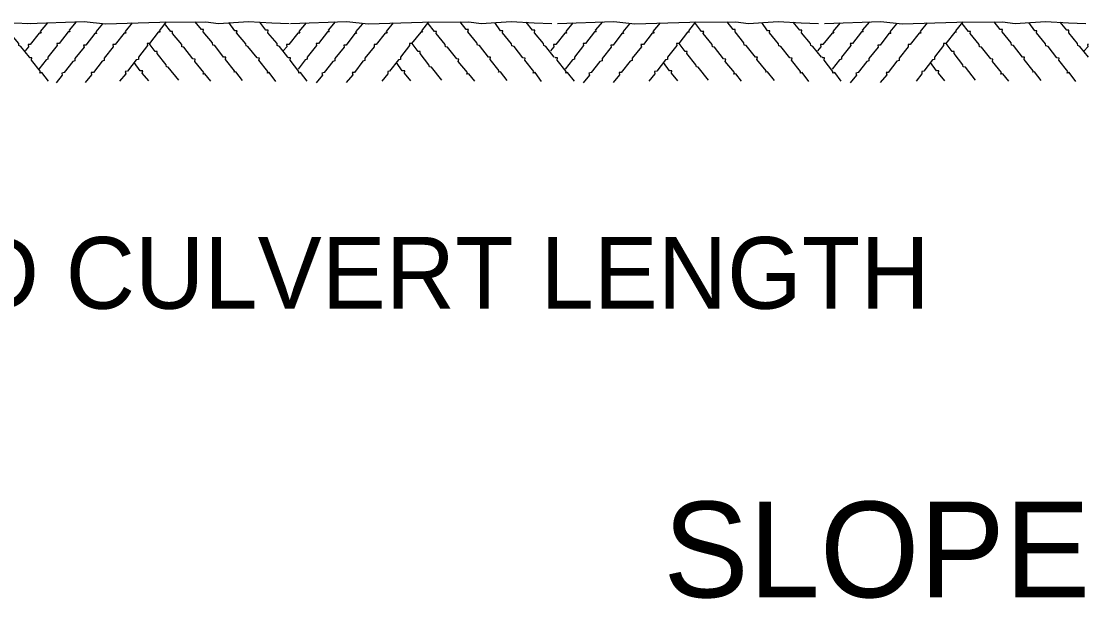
# Model space of a CAD drawing. Extents: x 49991.4 to 50021, y 49987.6 to 50011.4.
# Drawn here: x 50004.56 to 50005.452, y 49996.72 to 49997.202 of the extents above; entities that cross this region are included whole.
import ezdxf

# ---------------------------------------------------------------- set-up
doc = ezdxf.new("R2010")
doc.units = 0
doc.layers.add('Level 1', color=7, linetype='Continuous')
doc.layers.add('Level 2', color=7, linetype='Continuous')

msp = doc.modelspace()

# ---------------------------------------------------------------- linework, layer by layer
at = {"layer": 'Level 1'}
for points in [[(50004.3495, 49997.2006), (50004.3965, 49997.2025), (50004.4143, 49997.2004), (50004.4599, 49997.2019), (50004.4983, 49997.2022), (50004.5089, 49997.2007), (50004.534, 49997.2025), (50004.5533, 49997.2013), (50004.5679, 49997.2006)], [(50004.5669, 49997.1726), (50004.5597, 49997.1816), (50004.558, 49997.1822), (50004.5579, 49997.1839), (50004.5503, 49997.193), (50004.5505, 49997.195), (50004.5485, 49997.195), (50004.5433, 49997.2019)], [(50004.5655, 49997.2006), (50004.6125, 49997.2025), (50004.6303, 49997.2004), (50004.6759, 49997.2019), (50004.7143, 49997.2022), (50004.7249, 49997.2007), (50004.75, 49997.2025), (50004.7693, 49997.2013), (50004.7839, 49997.2006)], [(50004.5819, 49997.2012), (50004.5759, 49997.1941), (50004.5765, 49997.1926), (50004.5749, 49997.1926), (50004.5675, 49997.183), (50004.5665, 49997.183)], [(50004.6059, 49997.202), (50004.6, 49997.195), (50004.6005, 49997.1936), (50004.5993, 49997.1936), (50004.5917, 49997.184), (50004.5898, 49997.184), (50004.5899, 49997.1824), (50004.5823, 49997.1726), (50004.5823, 49997.171), (50004.5807, 49997.1704), (50004.5747, 49997.1626)], [(50004.6527, 49997.2012), (50004.6467, 49997.1941), (50004.6474, 49997.1926), (50004.6459, 49997.1926), (50004.6385, 49997.183), (50004.6365, 49997.183), (50004.6369, 49997.1812), (50004.6293, 49997.1718), (50004.6293, 49997.1698), (50004.6275, 49997.1692), (50004.6203, 49997.1598), (50004.6183, 49997.1598), (50004.6187, 49997.1578), (50004.6135, 49997.1515)], [(50004.6811, 49997.202), (50004.6753, 49997.1947), (50004.6761, 49997.1935), (50004.6745, 49997.1935), (50004.6671, 49997.1839), (50004.6653, 49997.1839), (50004.6654, 49997.1822), (50004.6579, 49997.1726), (50004.6579, 49997.1707), (50004.6559, 49997.1702), (50004.6489, 49997.1608), (50004.6469, 49997.1606), (50004.6474, 49997.1587), (50004.6421, 49997.1524)], [(50004.7449, 49997.153), (50004.7393, 49997.1602), (50004.7379, 49997.1599), (50004.7381, 49997.1612), (50004.7307, 49997.1706), (50004.7309, 49997.1725), (50004.7291, 49997.1726), (50004.7217, 49997.1824), (50004.72, 49997.1827), (50004.7199, 49997.1845), (50004.7121, 49997.1936), (50004.7123, 49997.1956), (50004.7105, 49997.1956), (50004.7053, 49997.202)], [(50004.7728, 49997.1522), (50004.7673, 49997.1596), (50004.7657, 49997.1592), (50004.7661, 49997.1605), (50004.7585, 49997.1701), (50004.759, 49997.1718), (50004.7571, 49997.172), (50004.7495, 49997.1816), (50004.7479, 49997.1821), (50004.7477, 49997.1838), (50004.7399, 49997.193), (50004.7404, 49997.1947), (50004.7385, 49997.1947), (50004.7335, 49997.2016)], [(50004.7829, 49997.1726), (50004.7757, 49997.1816), (50004.774, 49997.1822), (50004.7739, 49997.1839), (50004.7661, 49997.193), (50004.7665, 49997.195), (50004.7645, 49997.195), (50004.7593, 49997.2019)], [(50004.798, 49997.2012), (50004.792, 49997.1941), (50004.7927, 49997.1926), (50004.7913, 49997.1926), (50004.7837, 49997.183), (50004.7829, 49997.183)], [(50004.7849, 49997.2006), (50004.8321, 49997.2025), (50004.8499, 49997.2004), (50004.8955, 49997.2019), (50004.9341, 49997.2022), (50004.9445, 49997.2007), (50004.9695, 49997.2025), (50004.9888, 49997.2013), (50005.0035, 49997.2006)], [(50004.8225, 49997.202), (50004.8165, 49997.195), (50004.8173, 49997.1936), (50004.816, 49997.1936), (50004.8085, 49997.184), (50004.8065, 49997.184), (50004.8069, 49997.1824), (50004.7991, 49997.1726), (50004.7991, 49997.171), (50004.7974, 49997.1704), (50004.7914, 49997.1626)], [(50004.8709, 49997.2012), (50004.8649, 49997.1941), (50004.8657, 49997.1926), (50004.8641, 49997.1926), (50004.8567, 49997.183), (50004.8549, 49997.183), (50004.855, 49997.1812), (50004.8473, 49997.1718), (50004.8473, 49997.1698), (50004.8455, 49997.1692), (50004.8385, 49997.1598), (50004.8365, 49997.1598), (50004.837, 49997.1578), (50004.8317, 49997.1515)], [(50004.9003, 49997.202), (50004.8945, 49997.1947), (50004.8953, 49997.1935), (50004.8939, 49997.1935), (50004.8863, 49997.1839), (50004.8844, 49997.1839), (50004.8845, 49997.1822), (50004.8769, 49997.1726), (50004.8769, 49997.1707), (50004.8754, 49997.1702), (50004.8679, 49997.1608), (50004.8663, 49997.1606), (50004.8665, 49997.1587), (50004.8613, 49997.1524)], [(50004.9661, 49997.153), (50004.9607, 49997.1602), (50004.9589, 49997.1599), (50004.9594, 49997.1612), (50004.9519, 49997.1706), (50004.9523, 49997.1725), (50004.9504, 49997.1726), (50004.9429, 49997.1824), (50004.9413, 49997.1827), (50004.9408, 49997.1845), (50004.9333, 49997.1936), (50004.9337, 49997.1956), (50004.9318, 49997.1956), (50004.9269, 49997.202)], [(50004.9949, 49997.1522), (50004.9895, 49997.1596), (50004.9879, 49997.1592), (50004.9883, 49997.1605), (50004.9809, 49997.1701), (50004.9811, 49997.1718), (50004.9793, 49997.172), (50004.9719, 49997.1816), (50004.9701, 49997.1821), (50004.9697, 49997.1838), (50004.9623, 49997.193), (50004.9625, 49997.1947), (50004.9607, 49997.1947), (50004.9557, 49997.2016)], [(50005.0055, 49997.1726), (50004.9985, 49997.1816), (50004.9967, 49997.1822), (50004.9965, 49997.1839), (50004.9889, 49997.193), (50004.9893, 49997.195), (50004.9873, 49997.195), (50004.9821, 49997.2019)], [(50005.0211, 49997.2012), (50005.0151, 49997.1941), (50005.0158, 49997.1926), (50005.0143, 49997.1926), (50005.0069, 49997.183), (50005.0061, 49997.183)], [(50005.0081, 49997.2006), (50005.0554, 49997.2025), (50005.0729, 49997.2004), (50005.1189, 49997.2019), (50005.1573, 49997.2022), (50005.1679, 49997.2007), (50005.1928, 49997.2025), (50005.212, 49997.2013), (50005.2265, 49997.2006)], [(50005.0458, 49997.202), (50005.0398, 49997.195), (50005.0405, 49997.1936), (50005.0391, 49997.1936), (50005.0315, 49997.184), (50005.0297, 49997.184), (50005.0299, 49997.1824), (50005.0224, 49997.1726), (50005.0224, 49997.171), (50005.0207, 49997.1704), (50005.0145, 49997.1626)], [(50005.0939, 49997.2012), (50005.0879, 49997.1941), (50005.0889, 49997.1926), (50005.0873, 49997.1926), (50005.08, 49997.183), (50005.0779, 49997.183), (50005.0783, 49997.1812), (50005.0705, 49997.1718), (50005.0705, 49997.1698), (50005.0689, 49997.1692), (50005.0615, 49997.1598), (50005.0597, 49997.1598), (50005.0601, 49997.1578), (50005.0548, 49997.1515)], [(50005.1237, 49997.202), (50005.1177, 49997.1947), (50005.1184, 49997.1935), (50005.1169, 49997.1935), (50005.1095, 49997.1839), (50005.1077, 49997.1839), (50005.1079, 49997.1822), (50005.1003, 49997.1726), (50005.1003, 49997.1707), (50005.0985, 49997.1702), (50005.0913, 49997.1608), (50005.0893, 49997.1606), (50005.0897, 49997.1587), (50005.0845, 49997.1524)], [(50005.1895, 49997.153), (50005.1838, 49997.1602), (50005.1823, 49997.1599), (50005.1827, 49997.1612), (50005.1749, 49997.1706), (50005.1755, 49997.1725), (50005.1737, 49997.1726), (50005.1659, 49997.1824), (50005.1643, 49997.1827), (50005.1641, 49997.1845), (50005.1567, 49997.1936), (50005.1568, 49997.1956), (50005.155, 49997.1956), (50005.1499, 49997.202)], [(50005.2183, 49997.1522), (50005.2127, 49997.1596), (50005.2113, 49997.1592), (50005.2114, 49997.1605), (50005.2039, 49997.1701), (50005.2045, 49997.1718), (50005.2025, 49997.172), (50005.1949, 49997.1816), (50005.1933, 49997.1821), (50005.1929, 49997.1838), (50005.1853, 49997.193), (50005.1857, 49997.1947), (50005.1838, 49997.1947), (50005.1789, 49997.2016)], [(50005.2288, 49997.1726), (50005.2217, 49997.1816), (50005.2199, 49997.1822), (50005.2198, 49997.1839), (50005.2121, 49997.193), (50005.2125, 49997.195), (50005.2107, 49997.195), (50005.2053, 49997.2019)], [(50005.2444, 49997.2012), (50005.2384, 49997.1941), (50005.2391, 49997.1926), (50005.2377, 49997.1926), (50005.2301, 49997.183), (50005.2293, 49997.183)], [(50005.2315, 49997.2006), (50005.2785, 49997.2025), (50005.2963, 49997.2004), (50005.3419, 49997.2019), (50005.3803, 49997.2022), (50005.3909, 49997.2007), (50005.416, 49997.2025), (50005.4353, 49997.2013), (50005.4499, 49997.2006)], [(50005.269, 49997.202), (50005.263, 49997.195), (50005.2637, 49997.1936), (50005.2623, 49997.1936), (50005.2549, 49997.184), (50005.2528, 49997.184), (50005.2533, 49997.1824), (50005.2455, 49997.1726), (50005.2455, 49997.171), (50005.2438, 49997.1704), (50005.2378, 49997.1626)], [(50005.3173, 49997.2012), (50005.3113, 49997.1941), (50005.3119, 49997.1926), (50005.3105, 49997.1926), (50005.3031, 49997.183), (50005.3013, 49997.183), (50005.3014, 49997.1812), (50005.2937, 49997.1718), (50005.2937, 49997.1698), (50005.2919, 49997.1692), (50005.2847, 49997.1598), (50005.2829, 49997.1598), (50005.2834, 49997.1578), (50005.278, 49997.1515)], [(50005.3469, 49997.202), (50005.341, 49997.1947), (50005.3415, 49997.1935), (50005.3403, 49997.1935), (50005.3327, 49997.1839), (50005.3308, 49997.1839), (50005.3309, 49997.1822), (50005.3233, 49997.1726), (50005.3233, 49997.1707), (50005.3217, 49997.1702), (50005.3143, 49997.1608), (50005.3127, 49997.1606), (50005.3128, 49997.1587), (50005.3079, 49997.1524)], [(50005.4125, 49997.153), (50005.407, 49997.1602), (50005.4055, 49997.1599), (50005.4058, 49997.1612), (50005.3983, 49997.1706), (50005.3987, 49997.1725), (50005.3968, 49997.1726), (50005.3893, 49997.1824), (50005.3877, 49997.1827), (50005.3873, 49997.1845), (50005.3799, 49997.1936), (50005.3801, 49997.1956), (50005.3783, 49997.1956), (50005.3733, 49997.202)], [(50005.4415, 49997.1522), (50005.4358, 49997.1596), (50005.4343, 49997.1592), (50005.4347, 49997.1605), (50005.4273, 49997.1701), (50005.4275, 49997.1718), (50005.4257, 49997.172), (50005.4183, 49997.1816), (50005.4165, 49997.1821), (50005.4161, 49997.1838), (50005.4087, 49997.193), (50005.4089, 49997.1947), (50005.4071, 49997.1947), (50005.4021, 49997.2016)], [(50005.452, 49997.1726), (50005.4448, 49997.1816), (50005.4431, 49997.1822), (50005.443, 49997.1839), (50005.4355, 49997.193), (50005.4357, 49997.195), (50005.4339, 49997.195), (50005.4285, 49997.2019)], [(50004.6279, 49997.2004), (50004.6223, 49997.1936), (50004.6229, 49997.1923), (50004.6215, 49997.1923), (50004.6139, 49997.1827), (50004.6121, 49997.1827), (50004.6125, 49997.181), (50004.6048, 49997.1713), (50004.6048, 49997.1696), (50004.6031, 49997.1689), (50004.5958, 49997.1596), (50004.594, 49997.1593), (50004.5943, 49997.1576), (50004.5891, 49997.151)], [(50004.7185, 49997.1524), (50004.7135, 49997.1587), (50004.7121, 49997.1584), (50004.7125, 49997.1598), (50004.705, 49997.169), (50004.7053, 49997.171), (50004.7035, 49997.1712), (50004.696, 49997.1808), (50004.6943, 49997.1812), (50004.6941, 49997.183), (50004.6864, 49997.1922), (50004.6865, 49997.1941), (50004.6849, 49997.1941), (50004.6798, 49997.2006)], [(50004.8453, 49997.2004), (50004.8395, 49997.1936), (50004.8403, 49997.1923), (50004.8388, 49997.1923), (50004.8315, 49997.1827), (50004.8295, 49997.1827), (50004.8298, 49997.181), (50004.8221, 49997.1713), (50004.8221, 49997.1696), (50004.8205, 49997.1689), (50004.8131, 49997.1596), (50004.8113, 49997.1593), (50004.8117, 49997.1576), (50004.8064, 49997.151)], [(50004.939, 49997.1524), (50004.9341, 49997.1587), (50004.9325, 49997.1584), (50004.9329, 49997.1598), (50004.9253, 49997.169), (50004.9258, 49997.171), (50004.924, 49997.1712), (50004.9163, 49997.1808), (50004.9145, 49997.1812), (50004.9144, 49997.183), (50004.9067, 49997.1922), (50004.9071, 49997.1941), (50004.9053, 49997.1941), (50004.9001, 49997.2006)], [(50005.0683, 49997.2004), (50005.0629, 49997.1936), (50005.0635, 49997.1923), (50005.0621, 49997.1923), (50005.0547, 49997.1827), (50005.0529, 49997.1827), (50005.053, 49997.181), (50005.0455, 49997.1713), (50005.0455, 49997.1696), (50005.0435, 49997.1689), (50005.0363, 49997.1596), (50005.0345, 49997.1593), (50005.035, 49997.1576), (50005.0297, 49997.151)], [(50005.1621, 49997.1524), (50005.1573, 49997.1587), (50005.1557, 49997.1584), (50005.1561, 49997.1598), (50005.1485, 49997.169), (50005.149, 49997.171), (50005.1471, 49997.1712), (50005.1395, 49997.1808), (50005.1379, 49997.1812), (50005.1375, 49997.183), (50005.1299, 49997.1922), (50005.1304, 49997.1941), (50005.1285, 49997.1941), (50005.1235, 49997.2006)], [(50005.2917, 49997.2004), (50005.2859, 49997.1936), (50005.2869, 49997.1923), (50005.2853, 49997.1923), (50005.278, 49997.1827), (50005.2759, 49997.1827), (50005.2763, 49997.181), (50005.2685, 49997.1713), (50005.2685, 49997.1696), (50005.2669, 49997.1689), (50005.2595, 49997.1596), (50005.2577, 49997.1593), (50005.2581, 49997.1576), (50005.2528, 49997.151)], [(50005.3854, 49997.1524), (50005.3805, 49997.1587), (50005.3789, 49997.1584), (50005.3793, 49997.1598), (50005.3717, 49997.169), (50005.3721, 49997.171), (50005.3704, 49997.1712), (50005.3627, 49997.1808), (50005.3609, 49997.1812), (50005.3608, 49997.183), (50005.3531, 49997.1922), (50005.3535, 49997.1941), (50005.3517, 49997.1941), (50005.3465, 49997.2006)], [(50004.6917, 49997.1532), (50004.6829, 49997.1642), (50004.6813, 49997.1646), (50004.681, 49997.1662), (50004.6735, 49997.1755), (50004.6737, 49997.1773), (50004.672, 49997.1773), (50004.6669, 49997.1839)], [(50004.9114, 49997.1532), (50004.9029, 49997.1642), (50004.9011, 49997.1646), (50004.9007, 49997.1662), (50004.8933, 49997.1755), (50004.8935, 49997.1773), (50004.8917, 49997.1773), (50004.8867, 49997.1839)], [(50005.1345, 49997.1532), (50005.1259, 49997.1642), (50005.1243, 49997.1646), (50005.1239, 49997.1662), (50005.1163, 49997.1755), (50005.1167, 49997.1773), (50005.1148, 49997.1773), (50005.1099, 49997.1839)], [(50005.3577, 49997.1532), (50005.3493, 49997.1642), (50005.3473, 49997.1646), (50005.3471, 49997.1662), (50005.3397, 49997.1755), (50005.3398, 49997.1773), (50005.338, 49997.1773), (50005.3331, 49997.1839)], [(50004.5665, 49997.183), (50004.5658, 49997.183), (50004.5659, 49997.1812), (50004.5633, 49997.1778)], [(50004.7825, 49997.183), (50004.7817, 49997.183), (50004.7819, 49997.1812), (50004.7789, 49997.1778)], [(50005.0057, 49997.183), (50005.005, 49997.183), (50005.0051, 49997.1812), (50005.0023, 49997.1778)], [(50005.2289, 49997.183), (50005.2281, 49997.183), (50005.2283, 49997.1812), (50005.2255, 49997.1778)], [(50005.4521, 49997.183), (50005.4513, 49997.183), (50005.4515, 49997.1812), (50005.4485, 49997.1778)], [(50004.5827, 49997.1524), (50004.5773, 49997.1598), (50004.5755, 49997.1593), (50004.576, 49997.1606), (50004.5685, 49997.1701), (50004.5688, 49997.1719), (50004.5671, 49997.172), (50004.5665, 49997.1726)], [(50004.6665, 49997.1527), (50004.6611, 49997.1593), (50004.6615, 49997.1612), (50004.6595, 49997.1612), (50004.6543, 49997.168)], [(50004.7989, 49997.1524), (50004.7935, 49997.1598), (50004.792, 49997.1593), (50004.7921, 49997.1606), (50004.7847, 49997.1701), (50004.7849, 49997.1719), (50004.7833, 49997.172), (50004.7829, 49997.1726)], [(50004.8857, 49997.1527), (50004.8803, 49997.1593), (50004.8805, 49997.1612), (50004.8785, 49997.1612), (50004.8735, 49997.168)], [(50005.0223, 49997.1524), (50005.0165, 49997.1598), (50005.0151, 49997.1593), (50005.0155, 49997.1606), (50005.008, 49997.1701), (50005.0083, 49997.1719), (50005.0065, 49997.172), (50005.0061, 49997.1726)], [(50005.1088, 49997.1527), (50005.1034, 49997.1593), (50005.1039, 49997.1612), (50005.1019, 49997.1612), (50005.0967, 49997.168)], [(50005.2453, 49997.1524), (50005.2399, 49997.1598), (50005.2384, 49997.1593), (50005.2385, 49997.1606), (50005.2311, 49997.1701), (50005.2315, 49997.1719), (50005.2299, 49997.172), (50005.2293, 49997.1726)], [(50005.332, 49997.1527), (50005.3267, 49997.1593), (50005.3269, 49997.1612), (50005.3249, 49997.1612), (50005.32, 49997.168)]]:
    msp.add_lwpolyline(points, dxfattribs=at)

# ---------------------------------------------------------------- texts
at = {"layer": 'Level 2'}
for s, height, p in [('PLANNED CULVERT LENGTH', 0.06, (50004.1958, 49996.9622)), ('SLOPE DETAIL', 0.08, (50005.0967, 49996.72095))]:
    msp.add_text(s, height=height, dxfattribs=at).set_placement(p)

doc.saveas('drawing.dxf')
